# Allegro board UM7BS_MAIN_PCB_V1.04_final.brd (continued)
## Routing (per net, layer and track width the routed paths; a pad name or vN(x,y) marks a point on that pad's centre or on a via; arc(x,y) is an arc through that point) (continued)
USB_OC0#: length 293.4
  TOP w0.102: U1.P16 178.07,56.87 v1(178.07,56.83)
  LAY3 w0.102: v1(178.07,56.83) 178.28,56.63 178.28,56.02 178.07,55.81 177.74,55.81 177.43,55.5 177.43,55.25 174.52,52.34 174.52,50.11 174.68,49.95 174.68,48.47 174.26,48.05 174.26,42.66 175.74,41.18 175.74,40.16 176.23,39.67 v1(176.23,39.43) ; v1(47.45,27.59) 47.45,33.61 43.15,37.92 43.15,37.93 40.23,40.85 40.23,70.1 42.7,72.57 42.7,78.93 37.3,84.34 22.57,84.34 v1(20.42,82.19)
  LAY4 w0.102: v1(174.34,11.42) 172.67,9.75 153.55,9.75 151.07,12.24 146.8,12.24 144.78,10.22 140.71,10.22 140.25,10.68 130.46,10.68 127.77,13.36 115.94,13.36 112.28,9.7 98.55,9.7 95.91,12.35 92.03,12.35 89.42,9.74 70.45,9.74 66.8,13.39 57.24,13.39 54.79,15.85 49.31,15.85 47.45,17.7 v1(47.45,27.59)
  BOTTOM w0.102: v1(174.34,11.42) 174.15,11.62 174.15,15.09 174.79,15.74 174.79,26.85 172.71,28.93 172.71,37.03 174.97,39.28 176.08,39.28 v1(176.23,39.43) ; R89.1 176.42,53.05 176.42,53.41 176.93,53.91 176.93,54.42 177.36,54.85 177.36,55.62 177.54,55.79 178.07,55.79 178.22,55.95 178.22,56.68 v1(178.07,56.83)
  BOTTOM w0.203: U35.3 16.8,85.6 17.42,84.98 R472.1 19.47,84.98 R474.2 20.48,84.98 C441.1 20.49,82.26 v1(20.42,82.19)
USB_OC1#: length 165.5
  TOP w0.102: U1.P14 177.92,56.3 v1(177.82,56.2) ; v1(156.22,78.58) 156.22,76.66 158.04,74.84 158.04,64.4 v1(160.15,62.3)
  LAY3 w0.102: v1(156.22,78.58) 154.35,78.58 153.6,79.34 153.6,81.5 152.95,82.15 151.4,82.15 150.86,81.61 123.33,81.61 122.24,82.7 119.88,82.7 119.04,83.54 67.51,83.54 66.12,84.93 v1(60.08,84.93)
  BOTTOM w0.102: v1(160.15,62.3) 161.56,60.89 161.56,57.27 161.96,56.86 164.29,56.86 165.78,55.37 165.78,53.79 167.07,52.5 167.66,52.5 168.88,51.28 169.75,51.28 R88.1 170.85,52.38 170.85,53.12 171.27,53.54 171.68,53.54 172.5,54.36 172.5,54.69 172.99,55.18 176.24,55.18 177.26,56.2 v1(177.82,56.2) ; R481.2 53.64,91.95 60.08,85.51 v1(60.08,84.93)
  BOTTOM w0.203: R479.1 46.18,91.94 C448.1 ; C448.1 48.72,91.94 R481.2 ; C448.1 47.69,90.53 U38.3
USB_OC2#: length 86.4
  TOP w0.203: v1(42.07,25.66) R484.1 42.07,24.74 43.28,23.53 R486.2 43.48,23.28 C453.1 43.05,22.05 U39.3 ; U40.3 59.27,15.94 C458.1 58.13,17.28 R490.1 R491.2 58.29,20.09 57.4,20.98 57.4,28.21 56.32,29.29 56.32,30.07 57.53,31.29 59.01,31.29 v1(59.51,31.78)
  LAY3 w0.102: v1(61.8,52) 61.8,34.08 v1(59.51,31.78)
  BOTTOM w0.102: R467.1 44.2,55.29 47.63,51.86 61.66,51.86 v1(61.8,52)
  BOTTOM w0.203: v1(42.07,25.66) 42.07,26.48 47.12,31.53 59.26,31.53 v1(59.51,31.78)
USB_PN0: length 177.3
  TOP w0.089: 171.11,69.87 172.21,69.87
  TOP w0.101: 172.21,69.87 U1.B42 ; v1(167.25,74.99) 167.25,75.17 167.46,75.37 167.6,75.37 167.93,75.04 167.93,73.05 171.11,69.87
  TOP w0.124: FIL5.1 9,88.28 9,87.68 v1(9.36,87.32)
  LAY3 w0.112: v1(9.36,87.32) 9.22,87.32 8.83,87.71 8.83,88.1 8.97,88.24 13.42,88.24 13.87,87.79 26.44,87.79 27.97,86.25 49.35,86.25 50.03,86.93 66.65,86.93 68.21,85.37 107.9,85.37 108.38,84.89 117.73,84.89 118.07,85.23 123.26,85.23 124.65,83.84 126.75,83.84 127.06,84.15 139.61,84.15 140.52,83.23 148.17,83.23 148.34,83.39 153.95,83.39 160.55,76.79 164.69,76.79 166.19,75.29 166.72,75.29 166.83,75.18 166.83,74.82 166.93,74.72 167.11,74.72 167.25,74.86 v1(167.25,74.99)
USB_PN1: length 155.6
  TOP w0.101: 168.49,74.39 168.49,74.38 168.5,74.37 168.5,74.29 168.51,74.28 168.51,73.22 170.68,71.05 171.35,71.05 171.56,70.84 171.84,70.84 172.13,70.55 172.25,70.55 172.36,70.65 172.36,70.75 U1.B44
  TOP w0.124: 168.49,74.39 168.49,77.17 v1(168.24,77.42) ; v1(36.28,88.35) 36.28,88.95 FIL15.1
  LAY3 w0.112: v1(36.28,88.35) 36.51,88.58 36.51,88.75 36.42,88.85 35.85,88.85 35.75,88.94 35.75,89.37 35.9,89.52 36.42,89.52 37.07,88.86 49.09,88.86 50.05,89.82 58.89,89.82 59.62,89.1 67.53,89.1 69.36,87.27 90.52,87.27 91.69,88.44 94.28,88.44 95.45,87.27 113.67,87.27 115.5,89.1 124.09,89.1 126.09,87.11 127.89,87.11 129.02,88.24 129.9,88.24 131.02,89.35 135.82,89.35 136.94,88.24 144.64,88.24 147.35,85.52 154.03,85.52 161.19,78.36 167.99,78.36 168.58,77.77 168.58,77.52 168.47,77.42 v1(168.24,77.42)
USB_PN2: length 29.6
  TOP w0.089: 170.73,69.46 171.8,69.46 U1.A41
  TOP w0.102: 170.73,69.46 170.67,69.53 166.66,73.54 166.64,73.54 166.5,73.68 166.5,73.75 166.49,73.76 166.49,73.78
  TOP w0.124: FIL11.2 167.53,88.08 163.03,88.08 161.21,86.26 161.21,82.41 163.57,80.05 163.57,77.92 166.49,75 166.49,73.78
USB_PN3: length 158.5
  TOP w0.101: U1.A45 171.85,71.54 171.74,71.66 171.2,71.66 170.63,72.23 v1(170.39,72.23)
  TOP w0.124: v1(57.87,30.35) 58.12,30.1 58.12,29.72 58.14,29.72 58.14,21.95 59.51,20.58 61.16,20.58 FIL10.1
  LAY3 w0.112: v1(170.39,72.23) 170.15,72.23 169.99,72.39 169.29,72.39 168.74,72.94 159.66,72.94 155.83,69.11 155.83,61.77 151.02,56.97 148.67,56.97 147.12,55.41 112.93,55.41 110.2,58.15 106.19,58.15 100.83,52.78 97.67,52.78 95.25,50.35 84.15,50.35 80.13,46.34 80.13,36.65 73.57,30.09 60.42,30.09 59.67,29.34 58.47,29.34 58.13,29.68 58.13,30.09 v1(57.87,30.35)
USB_PN4: length 173.2
  TOP w0.089: U1.C40 172.67,68.92 172.37,68.62 172.12,68.62 172.01,68.73 171.6,68.73
  TOP w0.101: 166.46,72.61 166.65,72.61 166.72,72.61 170.59,68.73 171.6,68.73
  TOP w0.124: 166.46,72.61 165.67,72.61 164.62,73.66 164.62,74.52 164.91,74.81 v1(165.61,74.81) ; R485.1 45.68,20.42 45.21,20.42 44.7,20.92 44.7,22.8 49.66,27.76 v1(49.66,29.8)
  LAY3 w0.112: v1(49.66,29.8) 49.66,30.74 50.09,31.17 73.08,31.17 78.6,36.69 78.6,46.52 84.16,52.08 92.56,52.08 96.88,56.39 102.39,56.39 105.48,59.49 110.49,59.49 113.55,56.43 146.36,56.43 148.3,58.36 150.92,58.36 154.75,62.2 154.75,69.69 159.3,74.25 163.78,74.25 164.34,74.81 v1(165.61,74.81)
USB_PP0: length 177.3
  TOP w0.089: U1.C42 172.79,70.04 172.51,70.04 172.36,70.19 172.12,70.19 172.03,70.1 171.21,70.1
  TOP w0.101: 171.21,70.1 168.16,73.14 168.16,75.14 167.7,75.6 167.38,75.6 v1(167.25,75.73)
  TOP w0.124: FIL5.4 8.75,88.49 8.75,87.48 v1(8.59,87.32)
  LAY3 w0.112: v1(8.59,87.32) 8.59,88.2 8.87,88.48 13.52,88.48 13.97,88.02 26.54,88.02 28.07,86.49 49.25,86.49 49.93,87.17 66.74,87.17 68.31,85.61 108,85.61 108.48,85.13 117.63,85.13 117.97,85.47 123.36,85.47 124.75,84.08 126.65,84.08 126.96,84.38 139.7,84.38 140.62,83.47 148.08,83.47 148.24,83.63 154.05,83.63 160.65,77.03 164.79,77.03 166.29,75.53 167.06,75.53 v1(167.25,75.73)
USB_PP1: length 155.6
  TOP w0.101: 168.74,74.39 168.74,73.32 170.78,71.27 171.45,71.27 171.66,71.06 172,71.06 172.13,71.19 172.34,71.19 172.6,70.93 U1.C43
  TOP w0.124: v1(35.51,88.35) 35.51,88.88 FIL15.4 ; v1(168.98,77.42) 168.74,77.17 168.74,74.39
  LAY3 w0.112: v1(168.98,77.42) 168.82,77.58 168.82,77.87 168.09,78.6 161.29,78.6 154.13,85.76 147.45,85.76 144.74,88.48 137.04,88.48 135.92,89.59 130.92,89.59 129.8,88.48 128.92,88.48 127.8,87.35 126.18,87.35 124.19,89.34 115.4,89.34 113.57,87.51 95.55,87.51 94.37,88.68 91.59,88.68 90.42,87.51 69.46,87.51 67.63,89.34 59.72,89.34 58.99,90.06 49.95,90.06 48.99,89.1 37.17,89.1 36.52,89.76 35.81,89.76 35.51,89.47 v1(35.51,88.35)
USB_PP2: length 29.5
  TOP w0.089: 170.83,69.69 172.01,69.69 172.21,69.49 172.52,69.49 U1.C41
  TOP w0.102: 170.83,69.69 166.74,73.78
  TOP w0.124: 166.74,73.78 166.74,75.1 163.82,78.03 163.82,80.16 161.46,82.51 161.46,86.16 163.13,87.83 167.61,87.83 FIL11.3
USB_PP3: length 158.5
  TOP w0.101: U1.C45 172.51,71.44 172.28,71.44 171.84,71.88 171.3,71.88 v1(170.39,72.79)
  TOP w0.124: FIL10.4 61.43,20.83 59.62,20.83 58.39,22.05 58.39,29.97 58.39,29.97 58.38,29.97 58.38,30.1 v1(58.63,30.35)
  LAY3 w0.112: v1(58.63,30.35) 58.37,30.09 58.37,29.78 58.57,29.58 59.57,29.58 60.32,30.33 73.47,30.33 79.89,36.75 79.89,46.44 84.05,50.59 95.15,50.59 97.57,53.02 100.73,53.02 106.09,58.38 110.3,58.38 113.03,55.65 147.02,55.65 148.58,57.2 150.92,57.2 155.59,61.87 155.59,69.21 159.56,73.18 168.84,73.18 169.39,72.63 169.99,72.63 170.15,72.79 v1(170.39,72.79)
USB_PP4: length 173.2
  TOP w0.089: 171.6,68.94 171.82,68.94 172.14,69.26 172.34,69.26 172.46,69.13 172.46,69.02 172.37,68.92 U1.B40
  TOP w0.101: 171.6,68.94 170.71,68.94 166.81,72.83 166.49,72.83 166.46,72.86
  TOP w0.124: v1(50.43,29.8) 49.91,29.28 49.91,27.66 44.95,22.69 44.95,21.03 45.31,20.67 45.71,20.67 R483.1 ; 166.46,72.86 165.77,72.86 164.87,73.76 164.87,74.42 165.01,74.56 165.23,74.56 v1(165.61,74.18)
  LAY3 w0.112: v1(165.61,74.18) 165.61,74.1 165.44,73.94 165.24,73.94 165.13,74.05 165.13,74.47 165.02,74.57 164.44,74.57 163.88,74.01 159.4,74.01 154.99,69.59 154.99,62.1 151.02,58.13 148.4,58.13 146.46,56.19 113.45,56.19 110.39,59.25 105.58,59.25 102.49,56.15 96.98,56.15 92.66,51.84 84.25,51.84 78.84,46.43 78.84,36.59 73.18,30.93 50.19,30.93 49.9,30.64 49.9,30.32 49.98,30.24 50.48,30.24 50.6,30.12 50.6,29.93 50.47,29.8 v1(50.43,29.8)
V_DAC: length 12.6
  TOP w0.406: v1(107.81,38.41) C358.2 107.8,37.79 U23.6 ; v1(107.79,34.6) C350.2 107.78,33.98 U23.3
  BOTTOM w0.406: U24.6 107.78,35.24 C351.2 ; U24.3 107.81,39.05 C359.2 107.81,38.41 v1(107.81,38.41)
  BOTTOM w0.508: v1(107.81,38.41) 107.78,38.38 C351.2 107.79,35.24 v1(107.79,34.6)
VCLK: length 26.9
  BOTTOM w0.114: C177.1 C178.1 115.17,55.57 125.63,55.57 127.86,57.8 127.86,59.85 127.35,60.35 124.12,60.35 123.12,61.36 U10.19
VFB1: length 3.5
  BOTTOM w0.178: 122.04,59.62 121.9,59.62 121.6,59.93 U10.2
  BOTTOM w0.508: 122.04,59.62 122.23,59.62 122.75,59.1 R179.1 123.62,58.66 R180.2
VFB2: length 3.3
  BOTTOM w0.178: 120.63,59.41 120.63,59.51 120.8,59.68 U10.4
  BOTTOM w0.406: R181.1 120.44,59.22 120.63,59.41
  BOTTOM w0.508: R181.1 120.33,58.45 R183.1
VGG_GND: length 11.7
  TOP w0.178: v1(156.08,23.3) 156.24,23.3 156.35,23.19 U11.6
  TOP w0.406: R839.2 150.89,28.32 151.91,29.34 v1(153.03,29.34)
  LAY3 w0.406: v1(153.03,29.34) 153.65,28.72 153.65,25.91 156.08,23.48 v1(156.08,23.3)
VGG_LX: length 11
  TOP w0.178: U11.4 156.54,23.99 156.39,24.14 155.51,24.14 155.42,24.23
  TOP w0.305: 155.05,24.6 155.42,24.23
  TOP w0.635: 155.05,24.6 155.05,25.11 154.43,25.73 C211.2 154.18,27.55 154.76,28.13 154.76,31.99 155.13,32.36
VGG_SENSEN: length 94.7
  TOP w0.254: v1(156.39,26.71) 156.36,26.74 R826.1
  LAY3 w0.203: v1(191.36,37.52) 191.56,37.52 194.38,40.34 194.38,43.96 v1(193.94,44.4)
  LAY4 w0.203: v1(156.39,26.71) 156.83,26.27 156.83,25.5 157.29,25.03 157.29,22.01 156.48,21.2 153.89,21.2 v1(152.54,19.85)
  BOTTOM w0.203: v1(152.54,19.85) 152.05,20.33 151.63,20.33 151.31,20 151.31,17.95 151.6,17.65 151.6,15.47 151.21,15.09 151.21,11.99 152.97,10.23 183.05,10.23 187.79,14.97 187.79,23.36 191.36,26.92 v1(191.36,37.52) ; R770.2 194.08,44.54 v1(193.94,44.4)
VGG_SENSEN_R: length 22.2
  TOP w0.254: v1(182.88,59.95) 183.26,60.33 U1.AD22
  LAY3 w0.102: 187.21,59.64 187.21,60.11 186.99,60.33 183.26,60.33 v1(182.88,59.95)
  LAY3 w0.203: v1(193,47.05) 191.84,48.2 191.84,51.62 189.07,54.39 189.07,57.48 188.29,58.26 188.29,58.56 187.21,59.64
  BOTTOM w0.203: R770.1 194.08,46.74 193.78,47.05 v1(193,47.05)
VGG_SENSEP: length 91.3
  TOP w0.254: v1(156.04,26.12) 155.56,26.59 R105.1
  LAY3 w0.203: v1(194.57,44.87) 194.68,44.76 194.68,40.21 v1(190.87,36.4)
  LAY4 w0.203: v1(151.89,19.86) 153.53,21.5 156.36,21.5 156.99,22.13 156.99,24.9 156.48,25.42 156.48,25.68 v1(156.04,26.12)
  BOTTOM w0.203: R848.2 194.85,45.16 v1(194.57,44.87) ; v1(190.87,36.4) 190.87,27.15 187.38,23.66 187.38,15.24 182.67,10.53 153.09,10.53 151.52,12.11 151.52,14.68 151.96,15.13 151.96,18.15 151.62,18.49 151.62,19.59 v1(151.89,19.86)
VGG_SENSEP_R: length 23.5
  TOP w0.254: U1.AD24 183.26,61.09 v1(182.88,60.71)
  LAY3 w0.203: v1(182.88,60.71) 183.45,61.28 186.39,61.28 187.11,60.56 187.68,60.56 188.78,59.46 188.78,58.31 190.01,57.08 190.01,53.99 192.18,51.82 192.18,48.49 v1(193.02,47.65)
  BOTTOM w0.203: R848.1 194.85,46.7 194.11,47.44 193.23,47.44 v1(193.02,47.65)
VNN_SVID_SENSEP: length 42.2
  LAY3 w0.203: v1(171.07,39.7) 171.07,38.95 175.54,34.48 189.71,34.48 195.01,39.78 195.01,46.66 193.4,48.27 v1(193.05,48.27)
  BOTTOM w0.203: R109.1 168.07,40.07 170.7,40.07 v1(171.07,39.7) ; R565.2 193.23,48.09 v1(193.05,48.27)
VREFA: length 3.8
  BOTTOM w0.305: U41.12 117.26,85.55 C992.1 117.26,85.79 116.77,86.28 116.28,86.28 115.92,86.64 R616.2
VREG3: length 76.7
  TOP w0.406: v1(126.49,58.8) 125.5,57.82 v1(121.71,57.82) 121.45,57.82 v1(119.6,59.67)
  LAY3 w0.508: v1(118.7,80.09) 118.11,80.68 115.53,80.68 114.92,80.07 104.57,80.07 103.93,79.43 102.58,79.43 100.16,77.01 88.73,77.01 86.8,78.94 v1(84.51,78.94)
  LAY4 w0.508: v1(121.71,57.82) 119.94,57.82 117.64,60.11 117.64,73.52 118.7,74.57 v1(118.7,80.09)
  BOTTOM w0.178: 121.25,59.44 121.2,59.49 U10.3
  BOTTOM w0.381: v1(119.6,59.67) 118.18,59.67 R186.1
  BOTTOM w0.406: v1(126.49,58.8) 127.05,59.36 R185.2
  BOTTOM w0.508: v1(121.71,57.82) C156.1 121.71,58.98 121.25,59.44 ; D29.P v1(84.51,78.94)
VREG5: length 1.8
  BOTTOM w0.203: U10.13 121.2,63.87 121.64,64.31 C175.2
VSPI_KBC: length 15.1
  TOP w0.305: R460.2 U34.8 C427.1 R457.1 D12.N 44.36,77.6 v1(44.79,77.16) 45.48,76.47 R461.2
  BOTTOM w0.305: R449.1 49.05,75.87 47.76,77.16 v1(44.79,77.16)
WAKE_SCI_EC: length 16.8
  TOP w0.102: v1(65.56,65.08) 66.38,65.08 68.07,63.38 73.33,63.38 v1(74.54,62.16)
  TOP w0.114: R433.2 75.89,63.52 v1(74.54,62.16)
  BOTTOM w0.114: R438.1 v1(65.56,65.08) ; v1(74.54,62.16) 74.54,62.32 R434.1 75.78,63.56 U32.9
WIFI_3P3_RST#: length 2.8
  BOTTOM w0.102: U27.1 226.66,19.31 R364.2 226.04,21.27 Q39.3
WIFI_PCIE_RST: length 95.2
  TOP w0.114: U1.V12 180.57,54.68 v1(180.74,54.68)
  LAY3 w0.102: v1(201.13,23.77) 190.88,34.03 175,34.03 170.44,38.58 170.44,40.12 167.49,43.08 165.48,43.08 v1(164.25,44.31)
  LAY4 w0.102: v1(201.13,23.77) 218.76,23.77 221.71,20.82 v1(222.91,20.82)
  BOTTOM w0.101: 175.16,46.09 174.57,46.09
  BOTTOM w0.102: 174.57,46.09 171.61,43.14 165.44,43.14 164.26,44.31 v1(164.25,44.31) ; Q40.1 222.97,20.77 v1(222.91,20.82)
  BOTTOM w0.114: v1(180.74,54.68) 179.84,53.78 179.84,49.57 179.1,48.82 178.38,48.82 R115.1 178.3,48.57 178.06,48.33 177.39,48.33 175.16,46.09
WIFI_PERST#: length 3.5
  TOP w0.102: CN26.52 v1(229.57,16.02)
  BOTTOM w0.102: R372.1 228.57,16.02 v1(229.57,16.02)
  BOTTOM w0.114: U27.4 228.56,16.63 228.51,16.59 R372.1
WIFI_PWRON: length 244.6
  LAY3 w0.102: v1(52.52,68.74) 52.52,52.83 53.47,51.89 53.47,37.31 v1(53.13,36.97)
  LAY4 w0.102: v1(215.79,11.71) 214.45,10.38 183.21,10.38 180.73,12.86 173.11,12.86 170.91,10.67 154.81,10.67 152.84,12.64 152.31,12.64 151.22,13.72 145.87,13.72 143.38,11.23 141.22,11.23 140.67,11.78 130.5,11.78 127.38,14.91 110.4,14.91 106.37,18.94 106.37,45.76 104.43,47.7 98.07,47.7 88.11,37.74 70.7,37.74 68.55,35.59 58.97,35.59 57.59,36.97 v1(53.13,36.97)
  BOTTOM w0.102: v1(215.79,11.71) 218.06,11.71 218.2,11.85 R380.2 218.2,12.67 218.89,13.36 U28.3
  BOTTOM w0.114: U31.112 53.93,70.14 v1(52.52,68.74)
WIFI_RF_KILL_R*: length 2.1
  TOP w0.102: CN26.56 229.54,15.02 v1(229.37,15.19)
  BOTTOM w0.102: v1(229.37,15.19) 228.6,15.19 R193.1
WIRELESS_ON: length 235.5
  LAY3 w0.102: v1(60.33,54.14) 60.33,34.15 v1(60.02,33.84)
  LAY4 w0.102: v1(224.33,16.89) 224.33,14.67 219.83,10.16 182.89,10.16 180.51,12.55 173.26,12.55 171.18,10.46 154.68,10.46 152.75,12.39 152.06,12.39 150.94,13.51 145.99,13.51 143.49,11.02 141.11,11.02 140.71,11.42 130.58,11.42 127.31,14.69 110.25,14.69 105.94,19 105.94,45.7 104.31,47.34 98.04,47.34 87.99,37.29 72.34,37.29 68.89,33.84 v1(60.02,33.84)
  BOTTOM w0.102: R193.2 226,15.18 224.33,16.85 v1(224.33,16.89)
  BOTTOM w0.114: v1(60.33,54.14) U31.33
WP#: length 30.2
  TOP w0.102: v1(158.93,39.99) 159.11,40.18 U2.3 U4.3
  TOP w0.114: v1(179.6,48.2) 179.6,48.27 179.78,48.45 U1.U1
  BOTTOM w0.102: 160.6,41.6 158.48,41.6 158.26,41.39 R40.1
  BOTTOM w0.114: R40.1 158.93,40.4 v1(158.93,39.99) ; 160.6,41.6 162.6,43.6 164.12,43.6 165.06,42.65 171.95,42.65 174.11,44.82 175.13,44.82 176.68,46.36 176.68,46.84 177.69,47.86 179.26,47.86 v1(179.6,48.2)
WRST#: length 9.2
  TOP w0.102: v1(60.71,64.09) C422.2 R445.1 SW2.3 60.96,61.82 60.77,62 58.77,62 58.58,61.82 SW2.1
  BOTTOM w0.114: U31.14 60.98,65.06 60.71,64.79 v1(60.71,64.09)
XTAL1: length 8.2
  BOTTOM w0.114: X5.1 121.56,29.96 121.56,31.08 121.03,31.62 120.55,31.62 120.17,32 120.17,33.36 C324.1 120.73,33.92 U22.43
XTAL2: length 6
  BOTTOM w0.114: X5.3 120.34,30.94 119.15,32.13 119.15,33.36 C323.1 120.33,34.54 U22.44
XTAL25M_IN: length 18.5
  TOP w0.102: v1(177.44,60.64) 177.78,60.64 178.29,61.16 U1.P24
  TOP w0.114: X1.1 165.73,65.98 165.73,64.49 C12.2 166.27,63.07 R45.2 166.15,62.94 v1(166.15,62.46)
  LAY3 w0.127: v1(166.15,62.46) 167.09,61.51 171.81,61.51 172.05,61.27 176.81,61.27 v1(177.44,60.64)
XTAL25M_OUT: length 16.4
  TOP w0.114: X1.3 165.31,65.24 165.43,65.13 165.43,64.13 C13.2 165.26,63.14 R45.1 165.51,62.88 v1(165.51,62.46)
  TOP w0.127: U1.M22 177.05,60.27 v1(176.67,60.64)
  LAY3 w0.127: v1(176.67,60.64) 176.28,61.03 171.68,61.03 171.53,61.19 166.78,61.19 v1(165.51,62.46)
N46460: length 1.3
  TOP w0.114: v1(191.41,63.57) 191.41,63.38 U1.BA28
  BOTTOM w0.114: v1(191.41,63.57) 191.44,63.53 R1.1
N52618: length 1.3
  TOP w0.102: U1.G38 174.64,68.22 v1(174.64,68.39)
  BOTTOM w0.102: v1(174.64,68.39) 174.64,67.98 R15.2
N52622: length 1.3
  TOP w0.102: v1(174.01,68.42) 174.01,68.14 U1.F38
  BOTTOM w0.102: R15.1 174.01,67.85 v1(174.01,68.42)
N53865: length 1.2
  TOP w0.102: v1(174.77,73.6) 174.37,73.2 U1.F49
  BOTTOM w0.102: v1(174.77,73.6) 174.74,73.57 R17.2
N53869: length 1.2
  TOP w0.102: v1(174.77,72.71) 174.38,72.32 U1.F47
  BOTTOM w0.102: v1(174.77,72.71) 174.23,72.71 R17.1
N59327: length 2.4
  TOP w0.114: v1(178.79,71.25) 178.65,71.25 U1.P44
  BOTTOM w0.114: v1(178.79,71.25) 178.96,71.43 178.96,72.42 R16.1
N59478: length 6.6
  TOP w0.102: v1(177.82,55.31) 178.21,55.7 U1.P13
  BOTTOM w0.102: R20.1 178.4,50.33 178.4,54.73 v1(177.82,55.31)
N59568: length 5.1
  TOP w0.102: U1.P12 178.13,54.99 v1(177.82,54.68)
  BOTTOM w0.102: R21.1 177.33,51.15 177.33,54.19 v1(177.82,54.68)
N60711: length 3.8
  TOP w0.101: C4.1 169.46,61.06 169.56,61.16 169.56,61.52 169.67,61.62 169.92,61.62 170.42,61.12 172.03,61.12 172.04,61.13 172.22,61.13 U1.B24
N60715: length 4.2
  TOP w0.101: U1.C24 172.65,61.15 172.36,61.44 172.12,61.44 172.03,61.35 170.52,61.35 170.02,61.85 C3.1
N61460: length 12.4
  TOP w0.101: U1.C25 172.31,61.64 171.83,62.12 171,62.12 168.73,64.38 168.73,64.6 168.75,64.61 168.75,64.63
  TOP w0.124: C6.1 165.65,69.21 165.88,68.98 167.42,68.98 168.75,67.65 168.75,64.63
N61464: length 11.7
  TOP w0.101: U1.A25 171.85,61.77 171.73,61.89 170.9,61.89 168.49,64.3 168.49,64.63
  TOP w0.124: C5.1 165.65,68.44 165.94,68.73 167.31,68.73 168.49,67.55 168.49,64.63
N61983: length 12.2
  TOP w0.089: U1.AM14 186.74,56.07 v1(186.58,56.07)
  BOTTOM w0.114: v1(186.58,56.07) 186.07,55.56 186.07,52.33 185.79,52.05 185.79,51.67 187.09,50.38 187.09,49.13 189.63,46.59 R28.1
N61987: length 15.7
  TOP w0.089: v1(185.56,55.95) 186.03,56.41 U1.AK14
  BOTTOM w0.114: v1(185.56,55.95) 186.12,56.5 186.74,56.5 188.31,54.93 188.87,54.93 189.45,54.35 189.45,53.61 191.18,51.88 191.41,51.88 192.17,51.12 192.17,49.21 192.55,48.84 192.55,46.73 192.88,46.39 R29.1
N62557: length 1.3
  TOP w0.102: v1(173.88,61.66) 174.26,62.04 U1.F26
  BOTTOM w0.102: v1(173.88,61.66) 173.88,62.2 R35.2
N62561: length 1.4
  TOP w0.102: U1.D26 173.6,62.14 v1(173.12,61.66)
  BOTTOM w0.102: R35.1 173.02,61.75 v1(173.12,61.66)
N64250: length 1.9
  TOP w0.102: v1(176.67,64.58) 177.05,64.21 U1.M30
  BOTTOM w0.114: v1(176.67,64.58) 175.91,65.34 R25.2
N64254: length 1.7
  TOP w0.102: v1(177.31,64.58) 177.76,64.13 U1.N30
  BOTTOM w0.114: R25.1 176.77,65.12 v1(177.31,64.58)
N64675: length 4
  TOP w0.114: U1.AG1 184.92,49.52 184.92,49.09 R24.1
N64950: length 9.9
  TOP w0.114: U1.AF13 184.16,55.7 v1(184.55,55.31)
  BOTTOM w0.114: v1(184.55,55.31) 183.83,54.59 183.83,50.25 184.47,49.62 184.47,48 C7.1 R30.1
N65002: length 7.2
  TOP w0.114: U1.AF12 184.55,54.58 v1(184.55,54.55)
  BOTTOM w0.114: R33.1 184.94,48.94 184.74,49.14 184.74,50.33 184.12,50.95 184.12,54.12 v1(184.55,54.55)
N65040: length 5.9
  TOP w0.114: v1(182.77,53.28) 183.06,53.57 U1.AD9
  BOTTOM w0.114: R31.1 182.02,49.22 183.19,50.39 183.19,52.86 v1(182.77,53.28)
N65098: length 2.2
  TOP w0.114: U1.AD7 182.85,52.52 v1(182.77,52.52)
  BOTTOM w0.114: v1(182.77,52.52) 182.2,51.94 R32.1
N65529: length 8.8
  TOP w0.114: v1(184.55,56.07) 184.48,56.07 U1.AF14
  BOTTOM w0.114: R34.1 182.83,49.24 183.57,49.98 183.57,55.09 v1(184.55,56.07)
N66939: length 1.3
  TOP w0.203: U3.6 152.13,43.23 C10.2
N72611: length 1.2
  TOP w0.114: U1.P20 178.81,59.53 v1(178.81,59.63)
  BOTTOM w0.102: R46.2 178.81,59.81 v1(178.81,59.63)
N72676: length 8
  TOP w0.102: v1(178.07,59.63) 177.76,59.32 U1.N20
  BOTTOM w0.102: v1(178.07,59.63) 177.93,59.77 177.93,60.74 177.54,61.13 172.46,61.13 172.16,61.44 R47.2
N73559: length 44.4
  TOP w0.102: v1(177.45,61.66) 177.79,61.66 178.26,62.13 U1.P26
  LAY3 w0.127: v1(177.45,61.66) 177.45,61.74 177.09,62.1 168.94,62.1 v1(167.94,63.1)
  LAY4 w0.102: v1(167.94,63.1) 167.35,63.69 167.35,66.7 168.08,67.43 168.08,71.88 170,73.79 170,78.79 172.63,81.42 177.09,81.42 179.31,79.2 181.79,79.2 v1(182.87,80.28)
  BOTTOM w0.102: v1(182.87,80.28) 182.87,80.28 R44.2
N73565: length 7
  TOP w0.102: U1.AH45 185.23,71.65 v1(185.56,71.31)
  BOTTOM w0.114: R48.2 183.98,76.53 183.98,72.77 184.55,72.2 184.8,72.2 185.56,71.44 v1(185.56,71.31)
N73585: length 1.7
  BOTTOM w0.089: R49.2 183.68,78.64
  BOTTOM w0.102: R44.1 R49.2
  BOTTOM w0.114: 183.68,78.64 R48.1
N73829: length 4.7
  TOP w0.089: U1.A9 170.8,53.77 170.74,53.72 168.59,53.72 168.41,53.89
  TOP w0.102: 168.41,53.89 168.39,53.92 168.39,54.59 R50.2
N73942: length 9.1
  TOP w0.102: U1.AD51 183.19,74.63 183.53,74.97 183.53,75.1 183.39,75.24 183.39,75.74 183.02,76.11 183.02,76.65 182.64,77.03
  TOP w0.114: R51.2 179.46,81.19 R52.2 179.46,80.21 182.64,77.03
N74220: length 9
  TOP w0.102: 182.75,76.37 182.75,76.1 183.18,75.66 U1.AD52
  TOP w0.114: 182.75,76.37 182.75,76.49 180.87,78.36 180.08,78.36 178.93,79.52 178.93,80.3 178.52,80.71 R56.1 R53.2
N74266: length 13.4
  TOP w0.102: U1.AH50 185.39,73.47 v1(185.56,73.47)
  BOTTOM w0.102: R57.1 186.34,82.96 186.34,83.94 185.95,84.33 R54.2
  BOTTOM w0.114: v1(185.56,73.47) 184.5,74.54 184.5,81.12 R57.1
N74833: length 13.7
  TOP w0.102: U1.AH48 185.2,73.07 v1(185.56,72.71)
  BOTTOM w0.114: v1(185.56,72.71) 184.23,74.05 184.23,82.04 184.49,82.3 184.49,83.85 184.93,84.29 R55.1
N75113: length 11.4
  TOP w0.102: U1.AH51 185.32,74.53 185.32,74.8 185.44,74.92 185.44,75.16 185.33,75.26 185.33,78.02 ; R59.1 185.51,82.44 185.51,84.5 R58.2
  TOP w0.114: 185.33,78.02 185.33,81.07 185.95,81.68 R59.1
N75766: length 14.1
  TOP w0.114: R63.1 v1(184.93,83.63)
  LAY4 w0.102: v1(184.93,83.63) 184.93,84.45 183.66,85.72 183.26,85.72 176.92,92.05 v1(176.92,92.48)
  BOTTOM w0.102: Q5.3 v1(176.92,92.48)
N77258: length 5.2
  TOP w0.102: U1.AH40 185.21,68.8 v1(185.56,69.15)
  BOTTOM w0.102: v1(185.56,69.15) 185.13,69.59 185.13,71.53 184.72,71.95 184.2,71.95 R60.2
N79829: length 1.7
  BOTTOM w0.114: U5.5 114.6,44.81 114.97,44.44 115.14,44.44 115.27,44.31 R72.1
N80354: length 12.8
  TOP w0.102: v1(186.58,53.28) 186.79,53.28 U1.AM9
  BOTTOM w0.114: v1(186.58,53.28) 188.28,51.58 188.66,51.58 188.99,51.25 188.99,50.36 190.01,49.34 190.01,48.83 191.34,47.5 191.34,43.91 R65.1
N81322: length 1.9
  TOP w0.102: v1(173.88,65.6) 174.2,65.92 U1.F34
  BOTTOM w0.102: v1(173.88,65.6) 174.01,65.6 174.77,66.36 R94.2
N81326: length 1.6
  TOP w0.102: U1.D34 173.53,65.93 v1(173.19,65.6)
  BOTTOM w0.102: v1(173.19,65.6) 173.25,65.6 173.91,66.27 R94.1
N82446: length 3.1
  TOP w0.102: U1.B47 172.34,72.56 171.73,72.56 171.1,73.19 v1(171.1,73.19)
  BOTTOM w0.089: v1(171.1,73.19) 169.91,73.19 R91.1
N82527: length 2.6
  TOP w0.102: U1.A48 171.85,73.06 v1(171.1,73.82)
  BOTTOM w0.089: R92.1 v1(171.1,73.82)
N82633: length 1.4
  TOP w0.254: v1(177.44,67.5) 177.44,67.62 U1.N38
  BOTTOM w0.381: R100.2 177.02,67.09 v1(177.44,67.5)
N83371: length 3.7
  TOP w0.102: v1(176.93,55.31) 177.32,55.7 U1.M13
  BOTTOM w0.102: v1(176.93,55.31) 176.55,54.93 176.55,53.91 176.29,53.66 175.47,53.66 R80.2
N83609: length 1.6
  TOP w0.102: v1(178.83,51.88) 179.24,51.47 U1.T4
  BOTTOM w0.114: R93.2 179.09,51.63 v1(178.83,51.88)
N83745: length 3.6
  TOP w0.102: R85.2 177.69,47.38 178.32,48.02 U1.P2
N83769: length 3.3
  TOP w0.102: U1.R3 178.71,50.44 178.71,50.13 178.53,49.95 178.53,47.4 R87.2
N86700: length 19.2
  TOP w0.102: v1(175.91,57.72) 175.91,57.82 U1.K18
  LAY3 w0.127: v1(175.91,57.72) 175.4,58.23 172.99,58.23 172.1,57.34 172.1,56.96 171.34,56.2 166.05,56.2 v1(164.81,54.95)
  BOTTOM w0.114: v1(164.81,54.95) 164.62,55.14 R81.1 163.45,55.14 C20.2 163.44,55.26 162.88,55.82 161.59,55.82 161.11,55.34 X3.2
N86712: length 16.6
  TOP w0.102: U1.M18 176.67,57.87 v1(176.67,57.72)
  LAY3 w0.127: v1(176.67,57.72) 176.2,57.24 172.71,57.24 171.38,55.91 166.46,55.91 v1(164.79,54.24)
  BOTTOM w0.114: v1(164.79,54.24) 164.72,54.17 164.25,54.17 R81.2 163.44,54.19 C16.2 163.28,54.04 X3.1
N87028: length 4.9
  TOP w0.102: U1.F16 173.88,56.95 v1(173.88,56.83)
  BOTTOM w0.102: v1(173.88,56.83) 173.49,56.44 172.86,56.44
  BOTTOM w0.114: 172.86,56.44 172.11,56.44 170.77,55.11 C17.2
N87161: length 5
  TOP w0.102: U1.D18 173.25,57.93 v1(173.25,57.72)
  BOTTOM w0.114: v1(173.25,57.72) 173.14,57.62 171.07,57.62 R79.1 170.08,58.6 C19.1
N88012: length 6.9
  TOP w0.102: U1.J16 175.28,56.92 v1(175.28,56.83)
  BOTTOM w0.102: v1(175.28,56.83) 174.86,57.25 173.64,57.25
  BOTTOM w0.114: 173.64,57.25 170.4,57.25 R83.1 170.07,56.93 C18.1
N88403: length 2.5
  TOP w0.102: U1.G18 174.52,57.85 v1(174.52,57.72)
  BOTTOM w0.102: v1(174.52,57.72) 173.63,58.61 R84.1
N89664: length 20.9
  TOP w0.102: v1(177.44,56.83) 177.44,56.95 U1.N16
  BOTTOM w0.102: v1(177.44,56.83) 177.44,56.67 176.21,55.44 172.92,55.44 172.28,54.8 172.28,54.51 171.55,53.78 171.07,53.78 170.56,53.27 170.56,52.9 R90.1 169.72,53.03 166.83,53.03 166.02,53.84 166.02,55.51 163.66,57.86 Q53.2
N89704: length 3
  TOP w0.102: TP5.1 169.35,55.11
  TOP w0.114: U1.B12 172.14,55.22 171.03,55.22 170.92,55.11 169.35,55.11
N89904: length 2.6
  TOP w0.102: U1.AD40 183.12,68.8 v1(182.77,69.15)
  BOTTOM w0.114: v1(182.77,69.15) 182.77,69.66 182.11,70.33 R111.1
N912733: length 1.2
  TOP w0.089: v1(182.1,64.5) 182.09,64.5 U1.AA30
  BOTTOM w0.381: v1(182.1,64.5) 182,64.4 R129.1
N926610: length 2.9
  TOP w0.254: 174.95,49.22 174.95,49.75 U1.G1
  TOP w0.381: v1(174.92,47.66) C105.1 174.38,48.05 174.95,48.61 174.95,49.22
N936455: length 1.4
  TOP w0.114: v1(171.23,50.66) U1.A3
  BOTTOM w0.102: R135.1 171.29,50.72 v1(171.23,50.66)
N964422: length 1.6
  BOTTOM w0.203: LED1.1 178.04,97.37 U7.4
N967359: length 1.1
  BOTTOM w0.203: LED1.2 176.53,97.37 R145.2
N1003987: length 3
  TOP w0.114: CN1.198 v1(218.61,39.85)
  BOTTOM w0.203: v1(218.61,39.85) 218.74,39.98 R149.2 R146.2
N1049332: length 7.2
  BOTTOM w0.114: Q35.3 117.24,46.31 R308.2 119.72,45.94 119.72,43.08 119.93,42.87 U22.16
N1051586: length 2.5
  BOTTOM w0.102: R296.1 109.96,28.15 U21.4 C334.2
N1052520: length 12.9
  BOTTOM w0.102: CN6.7 86.06,23.78 85.64,24.2 85.64,27.58 88.75,30.7 90.43,30.7 90.83,31.1 90.83,31.5 FIL4.3
N1052530: length 6.1
  BOTTOM w0.102: FIL3.3 92.29,21.1 92.13,20.93 92.13,20.48 92.05,20.4 88.33,20.4 88.23,20.5 88.23,20.78 87.77,21.24 CN6.5
N1052610: length 17.2
  TOP w0.102: FIL2.2 93.42,32.57 93.07,32.22 92.57,32.22 92.28,31.92 92.28,28.36 91.32,27.41 91.32,22.57 89.5,20.75 88.77,20.75 88.52,21 88.52,21.57 CN6.6
N1052618: length 24.9
  TOP w0.102: FIL1.3 90.92,31.04 90.85,31.04 90.74,30.94 90.74,30.68 90.25,30.18 88.81,30.18 86.03,27.4 86.03,15.49 86.42,15.11 88.28,15.11 88.7,15.53 88.7,16.56 88.45,16.81 87.93,16.81 87.59,16.46 CN6.1
N1052644: length 25.7
  TOP w0.102: FIL1.2 90.44,30.8 90.12,30.48 88.69,30.48 85.73,27.52 85.73,15.37 86.29,14.81 88.41,14.81 89,15.4 89,16.68 88.57,17.11 87.91,17.11 CN6.2
N1052708: length 17.2
  TOP w0.102: FIL2.3 93.42,31.57 93.07,31.92 92.7,31.92 92.58,31.8 92.58,28.24 91.62,27.28 91.62,22.44 89.63,20.45 88.74,20.45 88.52,20.22 88.52,19.62 CN6.3
N1052848: length 5.1
  BOTTOM w0.102: CN6.4 87.72,20.1 FIL3.2
N1052868: length 13.3
  BOTTOM w0.102: FIL4.2 91.52,31.72 91.13,31.33 91.13,30.97 90.55,30.4 88.87,30.4 85.94,27.46 85.94,24.33 86.19,24.08 86.81,24.08 86.95,24.22 86.95,24.89 87.11,25.05 CN6.8
N1061129: length 2.1
  BOTTOM w0.178: R331.2 19.98,35.84 U25.33
N1061133: length 2.4
  BOTTOM w0.178: R332.2 19.93,34.89 20.54,35.5 21.3,35.5 21.36,35.44 U25.32
N1061141: length 2.3
  BOTTOM w0.203: C364.1 20.24,36.24 U25.34
N1061235: length 1.5
  BOTTOM w0.178: U25.1 28.86,37.04 C387.2
N1062073: length 6.4
  BOTTOM w0.178: R339.2 R340.2 26.76,28 27.32,28.56 27.32,31.08 27.03,31.38 U25.13
N1062173: length 3.4
  BOTTOM w0.178: U25.20 24.23,31.59 23.44,30.8 22.63,30.8 21.91,30.08 C378.2
N1062273: length 2.5
  BOTTOM w0.178: C379.2 24.63,31.58 U25.19
N1062851: length 6.3
  BOTTOM w0.102: R351.2 38.57,35.14 38.57,33 38.24,32.66 Q37.3 ; R351.2 39.17,35.75 U26.2 ; R351.2 39.17,36.57 R358.2
N1062939: length 1.3
  BOTTOM w0.102: Q38.1 R359.1
N1063057: length 5.9
  BOTTOM w0.102: Q37.1 36.98,31.71 37.27,31.42 R353.2 40.91,31.42 Q38.3
N1063545: length 6.8
  BOTTOM w0.114: U25.12 27.73,31.79 28.05,31.47 28.36,31.47 31.34,28.49 C384.2
N1063553: length 1.7
  BOTTOM w0.102: R342.1 32.19,27.44 R341.2 32.12,26.58 C384.1
N1064125: length 2.4
  BOTTOM w0.114: U25.7 28.84,34.64 29.4,34.08 C385.2
N1064657: length 1.9
  BOTTOM w0.178: R338.1 26.7,31.04 26.23,31.51 U25.15
N1064691: length 4
  BOTTOM w0.178: C375.1 20.75,39.39 20.75,38.73 21.73,37.74 U25.37
N1064695: length 7.9
  BOTTOM w0.178: U25.35 21.39,36.64 20.71,37.33 18.41,37.33 17.31,38.43 17.31,39.59 17.88,40.16 C375.2
N1064865: length 3
  BOTTOM w0.203: U25.27 21.32,33.44 19.72,31.84 C366.1
N1091368: length 1.5
  BOTTOM w0.305: R500.2 132.1,21.44 Q46.3
N1091486: length 2.6
  BOTTOM w0.508: Q45.3 135.47,27.56 R497.1
N1121703: length 9.5
  BOTTOM w0.114: X6.4 X7.2 63.15,74.38 R459.1 62.73,73.97 C425.1 62.22,72.32 60.87,70.97 60.87,70.09 61.1,69.86 U31.2
N1122397: length 9.7
  BOTTOM w0.114: X6.1 X7.1 63.4,75.58 R459.2 62.48,76 R458.2 C423.1 61.71,74.6 60.98,74.6 60.51,74.12 60.51,73.74 60.33,73.56 U31.128
N1123071: length 2.2
  BOTTOM w0.102: U31.93 44.32,69.06 R411.1
N1123827: length 2.6
  BOTTOM w0.114: U31.12 62.82,65.86 C424.1
N1123831: length 4.6
  BOTTOM w0.114: Q42.1 71.08,68.73 R413.2 71.86,67.09 Q43.3
N1124299: length 3.7
  BOTTOM w0.102: R450.1 51.23,74.26 51.23,73.85
  BOTTOM w0.114: 51.23,73.85 52.12,72.96 52.33,72.96 52.73,72.57 U31.109
N1124955: length 2.5
  BOTTOM w0.114: R442.2 58.95,73.3 58.73,73.08 U31.124
N1125039: length 1.6
  BOTTOM w0.114: R386.2 75.9,72.46 U29.5
N1125207: length 2.4
  BOTTOM w0.102: U31.84 45.1,65.46 44.58,65.97 R397.1
N1125735: length 3.9
  BOTTOM w0.114: U31.106 51.53,72.5 50.95,73.08 50.1,73.08 R449.2
N1125963: length 2.2
  BOTTOM w0.114: R428.1 63.8,61.86 U31.22
N1126063: length 9.2
  BOTTOM w0.178: 62.89,66.63 62.52,66.26 U31.11
  BOTTOM w0.203: D8.N 67.33,67.76 67.09,67.51 64.61,67.51 64.04,68.08 R410.1
  BOTTOM w0.381: 62.89,66.63 62.89,67.62 63.52,68.25 R410.1 R409.1
N1126133: length 6.2
  BOTTOM w0.114: R400.1 50.44,75.9 50.44,74.63 R403.1 50.67,73.39 51.17,73.39 51.93,72.63 U31.107
N1126239: length 5.2
  BOTTOM w0.102: D10.N 64.94,60.68 65.85,59.77 R430.2
  BOTTOM w0.114: U31.23 62.8,61.46 63.58,60.68 D10.N
N1126307: length 5.5
  BOTTOM w0.203: R444.1 59.46,75.9 59.46,74.63 R446.1 59.97,73.75 59.13,72.91 U31.125
N1126437: length 7.6
  BOTTOM w0.114: D11.N 67.46,71.81 66.95,71.3 64.16,71.3 63.94,71.08 R431.2 63.4,70.25 63.4,70.09 62.37,69.06 U31.4
N1126855: length 2.6
  BOTTOM w0.114: U31.113 54.33,73.67 R462.1
N1127021: length 5.1
  BOTTOM w0.114: R463.1 58.44,75.9 58.44,72.95 57.93,72.43 U31.122
N1127039: length 2
  BOTTOM w0.102: R439.1 54.37,55.36
  BOTTOM w0.114: 54.37,55.36 54.33,55.41 U31.48
N1127083: length 2.5
  BOTTOM w0.114: U31.77 45.58,62.66 44.67,63.57 R455.2
N1127147: length 5.6
  TOP w0.102: U34.3 49.55,73.85 49.07,74.33 R461.1
N1127169: length 2.1
  TOP w0.102: R460.1 48.28,81.36 U34.7
N1127267: length 2.2
  BOTTOM w0.114: R435.2 54.73,54.8 U31.47
N1127313: length 2.5
  BOTTOM w0.114: R438.2 63.4,65.08 62.58,64.26 U31.16
N1127321: length 8.1
  BOTTOM w0.114: U31.15 62.51,64.66 R422.2 64.45,65.58 65.88,65.58 67.83,63.63 D9.N
N1127467: length 2.4
  BOTTOM w0.114: R395.1 45.02,65.14 45.5,64.66 U31.82
N1127901: length 1.1
  BOTTOM w0.114: U30.12 77.46,69.5 R391.2
N1128819: length 1.1
  BOTTOM w0.114: U32.12 77.46,65.43 R427.2
N1129433: length 3.9
  BOTTOM w0.114: R398.1 46.51,73.74 47.12,73.14 48.09,73.14 48.73,72.5 U31.99
N1129705: length 6.8
  BOTTOM w0.114: R447.2 66.89,60.9 66.55,61.24 66.55,61.91 65.91,62.55 63.15,62.55 62.86,62.26 U31.21
N1129743: length 4.1
  BOTTOM w0.102: R404.1 47.07,72.75 48.04,72.75 48.33,72.46 U31.98
N5550068: length 9.7
  BOTTOM w0.114: U8.H5 178.23,29.12 178.06,28.96 177.36,28.96 176.04,30.28 176.04,30.87 175.87,31.04 175.87,32.83 175.76,32.95 175.46,32.95 175.35,33.06 175.35,33.29 175.46,33.41 175.76,33.41 175.87,33.52 175.87,33.75 175.76,33.86 175.46,33.86 175.35,33.98 175.35,34.21 175.46,34.32 175.76,34.32 175.87,34.44 R157.2
N5550072: length 8.5
  BOTTOM w0.076: 183.97,31.47 183.97,29.37 U8.W5
  BOTTOM w0.114: R576.2 186.54,35.08 R165.2 186.54,34.22 184.69,32.38 184.47,32.38 184.26,32.16 184.26,31.76 183.97,31.47
N5550076: length 9.5
  BOTTOM w0.076: U8.W6 183.48,29.36 183.48,31.5
  BOTTOM w0.114: R167.2 185.65,34.57 185.83,34.39 185.83,34.18 185.52,33.86 185.34,33.86 185.09,34.11 184.95,34.11 184.76,33.92 184.76,33.69 185.04,33.41 185.04,33.25 184.88,33.09 184.65,33.09 184.39,33.36 184.04,33.36 183.87,33.19 183.87,31.9 183.48,31.5
N5550080: length 9.8
  BOTTOM w0.114: R164.2 177.05,34.42 177.05,34.18 177.17,34.06 177.9,34.06 178.03,33.94 178.03,33.7 177.9,33.57 177.17,33.57 177.05,33.46 177.05,33.19 176.94,33.08 176.74,33.08 176.62,32.96 176.62,32.73 176.74,32.62 176.94,32.62 177.05,32.51 177.05,32.28 176.94,32.16 176.74,32.16 176.62,32.05 176.62,31.82 176.74,31.71 176.94,31.71 177.05,31.59 177.05,30.33 177.75,29.62 U8.H4
N5550084: length 5.4
  BOTTOM w0.076: U8.J2 178.96,30.88 178.96,31.52
  BOTTOM w0.102: 178.96,31.54 178.96,31.52
  BOTTOM w0.114: 178.96,31.54 178.96,32.08 181.21,34.33 R162.2
N5550116: length 9
  BOTTOM w0.076: 178.3,29.38 178.96,29.38 U8.J5
  BOTTOM w0.114: 178.3,29.38 178.07,29.38 178,29.31 177.52,29.31 176.4,30.43 176.4,31.12 176.25,31.28 176.25,33.47 176.37,33.58 176.64,33.58 176.76,33.7 176.76,33.93 176.64,34.04 176.37,34.04 176.25,34.15 176.25,34.51 R159.2
N5550120: length 7.1
  BOTTOM w0.114: R158.2 179.43,34.61 179.54,34.49 179.8,34.49 179.93,34.36 179.93,34.15 179.69,33.9 179.49,33.9 178.39,32.81 178,32.81 177.79,32.61 177.79,30.64 178.31,30.12 U8.H3
N5550124: length 7.6
  BOTTOM w0.076: 182.98,31.42 182.98,29.36 U8.U5
  BOTTOM w0.114: 182.98,31.42 183.08,31.52 183.08,32.97 184.76,34.65 R169.2 R168.2
N5550128: length 9.6
  BOTTOM w0.076: 178.41,28.88 178.96,28.88 U8.J6
  BOTTOM w0.114: R156.2 174.98,32.67 175.38,32.27 175.38,30.41 177.21,28.58 178.11,28.58 178.41,28.88
N5550132: length 9.1
  BOTTOM w0.076: 178.16,29.9 178.18,29.88 178.96,29.88 U8.J4
  BOTTOM w0.114: 178.16,29.9 178.05,29.9 177.42,30.54 177.42,33.03 177.57,33.18 178.25,33.18 178.42,33.36 178.42,33.74 178.54,33.86 178.9,33.86 179.14,34.1 179.14,34.32 179.02,34.44 178.32,34.44 178.16,34.6 178.16,34.9 178.27,35.02 R161.2
N5550136: length 6.5
  BOTTOM w0.076: 178.48,30.38 178.96,30.38 U8.J3
  BOTTOM w0.114: R160.2 180.32,34 178.24,31.92 178.24,30.6 178.45,30.38 178.48,30.38
N5560544: length 1.2
  BOTTOM w0.102: U6.12 77.46,60.17 R125.2
N5591752: length 3.9
  TOP w0.178: R196.1 158.12,27.98 159.64,26.46 U11.60
  TOP w0.203: R195.2 R196.1
N5595026: length 4.4
  TOP w0.102: R206.2 R203.2
  TOP w0.114: U11.14 156.8,19.99 155.69,18.87 155.69,18.19 155.29,17.8 R206.2
N5595322: length 23.6
  TOP w0.178: v1(161.48,27.55) 161.64,27.39 U11.55
  BOTTOM w0.508: R194.2 150.06,19.02 150.31,19.27 150.31,22.36 152.85,24.9 152.85,26.58 156.45,30.18 160.98,30.18 161.56,29.6 C183.2 161.56,27.62 v1(161.48,27.55)
N5595880: length 2.3
  TOP w0.178: U11.53 162.44,28.26 C187.1
N5599060: length 10.6
  TOP w0.102: v1(150.08,17.36) 150.55,17.83 Q52.3
  TOP w0.114: U11.15 156.75,19.59 156.46,19.31 156.46,19.09 v1(156.38,19)
  LAY4 w0.102: v1(150.08,17.36) 150.08,18.02 151.51,19.46 155.91,19.46 v1(156.38,19)
  BOTTOM w0.102: v1(156.38,19) 156.31,18.93 R207.1
N5599220: length 4.3
  TOP w0.102: R208.2 R558.1 155.48,16.94
  TOP w0.114: 155.48,16.94 157.1,18.56 157.1,19.15 U11.16
N5599311: length 4.7
  TOP w0.114: U11.27 162.04,17.79 162.59,17.24 162.59,15.17 v1(162.66,15.09)
  BOTTOM w0.102: R589.2 162.4,15.09 v1(162.66,15.09)
N5599330: length 1.9
  TOP w0.114: v1(162,17.23) 161.64,17.59 U11.26
  BOTTOM w0.102: v1(162,17.23) 161.7,16.93 R210.2
N5599357: length 47.8
  TOP w0.114: v1(163.34,15.81) 163.16,15.81 162.89,16.09 162.89,17.28 162.44,17.73 U11.28
  LAY4 w0.102: v1(165.88,15.07) 165.88,15.64 165.29,16.23 165.29,21.57 170.87,27.15 173.88,27.15 174.38,26.65 180.52,26.65 180.97,26.19 187.76,26.19 192.96,31.38 v1(194.69,31.38)
  BOTTOM w0.102: v1(165.88,15.07) 165.88,15.46 165.53,15.81 v1(163.34,15.81) ; v1(194.69,31.38) 194.7,31.39 R588.2
N5601032: length 3.6
  TOP w0.178: U11.35 165.43,19.99 165.59,19.83 166.08,19.83
  TOP w0.381: 166.08,19.83 167.1,18.8 C223.2
N5603445: length 2.4
  TOP w0.178: U11.30 163.24,17.76 164.18,16.81 R211.1
N5604033: length 3.2
  TOP w0.178: U11.5 156.47,23.59 156.27,23.79
  TOP w0.203: 156.27,23.79 154.62,23.79 154.57,23.84
  TOP w0.508: C211.1 154.57,23.84
N5614603: length 1.8
  BOTTOM w0.178: U10.17 123.41,62.16 C165.1
N5614763: length 3.5
  BOTTOM w0.178: R182.2 123.76,59.25 122.65,60.36 U10.1
N5615595: length 3.6
  BOTTOM w0.178: R184.1 118.67,59.22 119.8,59.22 120.4,59.82 U10.5
N5615857: length 2.1
  BOTTOM w0.178: U10.9 119.39,62.16 118.3,63.25 C166.2
N5617013: length 2
  TOP w0.178: v1(157.28,25.65) 157.71,26.08 158.03,26.08 U11.64
  BOTTOM w0.203: v1(157.28,25.65) 157.28,25.26 R198.2
N5627138: length 3.3
  TOP w0.178: U11.41 165.42,22.39
  TOP w0.203: C213.2 167.23,22.19 165.62,22.19 165.42,22.39
N5627940: length 2.4
  TOP w0.178: 165.61,23.99 165.65,24.03 166.39,24.03 v1(166.44,24.08)
  TOP w0.203: U11.45 165.61,23.99
  BOTTOM w0.305: v1(166.44,24.08) 166.45,24.09 R200.1
N6484561: length 2.7
  BOTTOM w0.102: R454.2 44.62,59.93 45.75,61.06 U31.73
N6547424: length 2.5
  TOP w0.203: R259.2 R260.2 149.87,100.39 v1(150.71,100.39)
  BOTTOM w0.152: U16.45 v1(150.71,100.39)
N6549298: length 1.7
  TOP w0.203: U17.7 139.91,96.65 R269.1
N6549760: length 1.9
  BOTTOM w0.102: R268.1 153.05,91.88 153.11,91.94 U16.20
N6556930: length 6.9
  TOP w0.124: CN3.S5 102.36,73.74 102.75,73.35 103.07,73.35 103.33,73.09 103.33,72.44 103.64,72.13 105.87,72.13 106.24,71.75 106.24,71 C433.2
N6556942: length 5.8
  TOP w0.124: CN3.S2 102.98,77.55 103.17,77.35 105.62,77.35 106.24,76.74 106.24,76.34 C429.2
N6556946: length 5.8
  TOP w0.124: CN3.S3 102.98,76.28 103.49,76.78 103.49,76.97 103.61,77.1 105.52,77.1 105.99,76.63 105.99,76.38 C432.2
N6556996: length 6.9
  TOP w0.124: CN3.S6 101.52,72.81 101.81,73.1 102.97,73.1 103.08,72.98 103.08,72.33 103.54,71.87 105.76,71.87 105.99,71.65 105.99,71.17 C434.2
N6563019: length 4.1
  TOP w0.124: J4.3 7.95,92.97 8.86,92.07 8.86,91.84 D14.N 8.53,90.56 FIL5.3
N6563079: length 4.1
  TOP w0.124: FIL7.2 12.32,90.38 U37.2 12.43,91.14 12.43,92.32 12.95,92.84 J4.9
N6563083: length 4.2
  TOP w0.124: FIL7.3 11.62,90.46 U37.1 11.43,91.23 11.43,92.27 10.95,92.74 J4.8
N6563115: length 4.1
  TOP w0.124: J4.2 9.95,92.96 9.11,92.11 9.11,91.84 D13.N 9.44,90.55 FIL5.2
N6563127: length 3.8
  TOP w0.124: FIL6.3 5.55,90.97 U36.1 5.78,91.77 5.78,91.94 4.95,92.76 J4.5
N6564657: length 0.9
  TOP w0.124: C442.1 11.43,87.6 FIL7.4
N6564689: length 3.8
  TOP w0.124: FIL6.2 6.25,90.9 U36.2 6.03,91.76 6.03,91.94 6.95,92.86 J4.6
N6564811: length 5.3
  TOP w0.124: FIL10.3 D20.N 64.88,20.7 67.17,20.7 CN20.3
N6564823: length 5.2
  TOP w0.124: FIL10.2 D19.N 64.88,20.44 67.33,20.44 CN20.2
N6564845: length 0.9
  TOP w0.124: FIL7.1 12.43,87.6 C443.1
N6565949: length 5.1
  TOP w0.124: FIL9.4 47.83,20.03 D17.N 49.25,20.03 49.68,20.45 51.6,20.45 CN19.2
N6565995: length 5.1
  TOP w0.124: CN19.3 51.46,20.71 49.61,20.71 49.29,21.03 D18.N 47.83,21.03 FIL9.1
N6570497: length 3.8
  BOTTOM w0.203: Q51.3 148.77,83.97 149.16,84.36 R540.2 149.89,86.02 Q50.1
N6570755: length 3.8
  BOTTOM w0.203: R537.2 101.3,90.9 Q48.1 101.3,92.8 101,93.09 Q49.3
N6595992: length 2.1
  BOTTOM w0.102: U31.57 50.73,55.31 R552.1
N6596046: length 3.2
  BOTTOM w0.178: U10.7 119.42,61.36 119.19,61.13 118.37,61.13 R187.1
  BOTTOM w0.203: R187.1 118.02,61.38 117.26,62.14 R188.2
N6633155: length 3.7
  BOTTOM w0.305: R347.1 C394.1 J2.4
N6633185: length 3.7
  BOTTOM w0.305: J2.3 28.55,19.01 28.75,19.22 C393.1 R348.1
N6635302: length 7.1
  TOP w0.305: J3.3 28.12,27.93 23.49,27.93 C399.1 22.71,27.53 R352.1
N6635336: length 13.7
  TOP w0.305: R354.1 27.66,31 C398.1 30,30.57 30,29.29 31.23,28.07 34.36,28.07 34.65,28.35 J3.4
N6638078: length 1.2
  BOTTOM w0.305: R334.1 21.84,27.65 C378.1
N6638082: length 1.2
  BOTTOM w0.305: C379.1 23.12,27.66 R336.1
N6697991: length 3.3
  BOTTOM w0.203: 135.94,85.2 135.94,85.89 135.24,86.59 R249.2
N6698007: length 2
  BOTTOM w0.203: C286.2 136.19,88.25 R249.1 136.19,87.1 U15.4
N6698131: length 9.5
  TOP w0.102: v1(134.74,87.43) 135.21,86.95 135.21,85.85 134.95,85.58 133.51,85.58 R251.2 131.23,86.39 Q30.3
  BOTTOM w0.203: v1(134.74,87.43) 134.4,87.76 133.93,87.76 R255.1 133.2,88.08 133.2,87.33 133.44,87.1 U15.3
N6698734: length 5.7
  TOP w0.102: R253.2 132.7,87.34 Q30.1 128.61,87.34 127.66,86.39 Q31.3
N6729809: length 1.4
  BOTTOM w0.203: D5.3 111.93,59.76 C178.2
N6729821: length 3
  BOTTOM w0.203: C181.1 D4.2 D5.1
N6730049: length 3.7
  BOTTOM w0.203: D4.3 110.46,61.11 111.12,60.45 C177.2
N6738242: length 29.1
  BOTTOM w0.305: Q18.4 140.91,62.83 141.89,61.85 148.83,61.85 149.16,61.52 153.26,61.52 154.27,62.53 R217.1 C256.2
N6738428: length 2
  BOTTOM w0.203: Q21.4 C260.2 R222.1
N6738432: length 7.4
  BOTTOM w0.305: Q20.3 155.67,67.95 156.57,68.85 156.57,69.27 157.67,70.37 Q19.1 R216.2 R218.2
N6738496: length 1.4
  BOTTOM w0.203: Q20.1 R219.2
N6739070: length 6
  BOTTOM w0.203: Q23.3 109.63,78.15 111.63,76.15 Q22.1 112.34,75.99 R221.2 113.06,77.55 R224.2
N6739082: length 5.5
  BOTTOM w0.203: R220.2 112.42,74.63 110.89,74.63 110.48,75.04 Q22.3 108.78,75.04 R222.2
N6739106: length 1.1
  BOTTOM w0.203: Q23.1 111.62,79.55 R223.2
N6774197: length 5.5
  BOTTOM w0.508: CN24.1 36.42,74.06 R551.2
N6774217: length 1.3
  BOTTOM w0.508: R551.1 D26.P
N6835771: length 28.8
  TOP w0.381: CN21.D 115.75,18 117.89,15.85 127.89,15.85 128.93,16.9 v1(131.58,16.9)
  BOTTOM w0.508: R494.1 139.43,19.32 138.76,18.65 138.76,18.54 136.71,16.48 131.99,16.48 v1(131.58,16.9)
N6920056: length 2.3
  BOTTOM w0.203: R554.1 C268.2 166.37,36.03 U44.4
N6920082: length 2.6
  BOTTOM w0.305: R559.1 166.35,31.21 R234.2 166.36,31.88 166.37,31.88 U44.3
N6950647: length 1.4
  BOTTOM w0.203: U46.1 142.05,46.01 R557.2
N7015906: length 8.7
  TOP w0.102: U1.AF3 184.15,50.59 183.86,50.31 183.86,50.04 184.09,49.81 184.09,49.34
  TOP w0.114: TP10.1 184.89,43.74 184.89,47.58 184.09,48.38 184.09,49.34
N7019072: length 3.2
  BOTTOM w0.102: Q53.3 159.99,58.83 R592.1 157.71,58.83 R97.1 R95.1
N7027378: length 2.5
  BOTTOM w0.102: 62.86,62.76 62.76,62.66 U31.20
  BOTTOM w0.114: R562.1 63.48,63.38 62.86,62.76
N7088826: length 25.1
  TOP w0.254: v1(182.88,62.23) 182.5,62.61 U1.AC27
  LAY3 w0.203: v1(195.12,48.08) 195.72,48.69 195.72,49.6 194.85,50.47 194.85,56.95 194.54,57.27 191.12,57.27 189.14,59.25 189.14,59.87 188.07,60.94 187.2,60.94 186.48,61.66 183.45,61.66 v1(182.88,62.23)
  BOTTOM w0.203: v1(195.12,48.08) 195.11,48.09 R565.1
N7139654: length 1.5
  BOTTOM w0.102: R113.1 176.1,81.71 Q6.3
N7139690: length 1.3
  BOTTOM w0.102: Q7.3 R123.1
N7139951: length 1.2
  TOP w0.089: U1.U51 179.78,74.14 v1(179.82,74.1)
  BOTTOM w0.102: R567.2 179.84,74.13 v1(179.82,74.1)
N7142786: length 7.9
  TOP w0.102: U1.V4 180.28,51.42 181.22,50.48 181.35,50.48 181.53,50.31 181.53,50.05 181.37,49.89 181.37,49.85
  TOP w0.114: 181.37,49.85 181.37,49.67 181.63,49.42 181.63,48.58 v1(180.99,47.94)
  BOTTOM w0.114: R37.2 179.62,45.95 179.89,46.21 179.89,46.71 180.48,47.31 180.48,47.69 180.74,47.94 v1(180.99,47.94)
N7142796: length 7.3
  TOP w0.102: 180.54,47.77 180.54,49.31 180.47,49.38 180.47,49.95 180.61,50.09 180.61,50.25 180.27,50.59 U1.V3
  TOP w0.114: 180.54,47.77 v1(180.99,47.31)
  BOTTOM w0.114: R38.2 179.36,45.11 180.29,46.04 180.29,46.74 180.87,47.31 v1(180.99,47.31)
N7142806: length 7.2
  TOP w0.102: U1.V2 180.27,47.4
  TOP w0.114: 180.27,47.4 v1(180.99,46.67)
  BOTTOM w0.114: R39.2 179.3,44.26 180.99,45.95 v1(180.99,46.67)
N7142816: length 5.5
  TOP w0.102: 181.25,48.83 181.42,49.01 181.42,49.33 181.16,49.59 181.16,49.83 180.92,50.06 180.92,50.37 U1.W3
  TOP w0.114: 181.25,48.83 v1(180.99,48.58)
  BOTTOM w0.114: R36.2 179.42,46.75 180.1,47.44 180.1,48.07 180.61,48.58 v1(180.99,48.58)
N7143552: length 5.3
  TOP w0.114: U1.V13 180.64,55.31 v1(180.74,55.31)
  BOTTOM w0.114: R569.2 181.25,51.54 181.25,54.8 v1(180.74,55.31)
N7143994: length 2.1
  TOP w0.114: v1(181.75,55.31) 181.62,55.31 U1.Y13
  BOTTOM w0.114: v1(181.75,55.31) 182.64,54.42 TP11.1
N7144188: length 11.6
  TOP w0.114: U1.AF6 184.36,52.2 v1(184.68,52.52)
  BOTTOM w0.114: v1(184.68,52.52) 184.68,52.48 186.85,50.31 186.85,48.53 188.7,46.68 R573.1 188.19,45.87 188.19,44.09 R570.1
N7144196: length 10.7
  TOP w0.114: U1.AH6 184.94,52.14 v1(184.68,51.88)
  BOTTOM w0.114: v1(184.68,51.88) 184.92,51.88 186.6,50.2 186.6,48.25 187.69,47.16 R572.1 187.15,45.84 187.15,44.11 R571.1
N7380328: length 2.1
  TOP w0.203: D28.N 131.49,9.47 Q1.1
N7380332: length 0.9
  TOP w0.203: R3.1 C2.1
N7537612: length 17.4
  TOP w0.102: U1.BA26 191.71,62.12 v1(192.17,61.66)
  LAY3 w0.102: v1(192.17,61.66) 193.23,60.6 194.19,60.6 195.48,59.31 195.48,58.57 198.19,55.86 v1(198.19,48.52)
  BOTTOM w0.102: R593.1 v1(198.19,48.52)
N7539259: length 2.9
  TOP w0.076: v1(172.44,76.01) 172.49,76.06 172.95,76.06 173.2,75.8 173.2,75.74 173.25,75.34 173.1,75.15 172.94,75.13 172.88,75.13 U1.B52
  BOTTOM w0.102: R594.2 172.58,75.87 v1(172.44,76.01)
N7546529: length 9.5
  TOP w0.076: U1.BH52 195.08,74.63 195.2,74.29 195.3,74.11 195.38,74.03
  TOP w0.102: R595.2 198.09,80.21 198.09,75.98 196.84,74.74 195.98,74.74 195.83,74.59 195.83,74.23 195.62,74.03 195.38,74.03
N7553859: length 9.8
  BOTTOM w0.102: U8.H6 178.55,28.62 178.14,28.21 177.07,28.21 175,30.28 175,32.14 174.14,33 R599.1
N7556393: length 120.1
  TOP w0.114: U1.A13 171.77,55.73 170.35,55.73 169.89,56.18 165.17,56.18 163.42,57.93 149.88,57.93 148.79,56.84 138.38,56.84 137.4,55.87 123.2,55.87 120.73,53.4 111.32,53.4 109.66,51.73 106.36,51.73 105.78,52.31 105.78,66.7 103.37,69.11 95.59,69.11 86.52,60.04 v1(84.83,60.04)
  BOTTOM w0.102: R605.1 79.11,56.04 79.81,55.34 82.87,55.34 84.83,57.31 v1(84.83,60.04)
N7556465: length 117.7
  TOP w0.102: U1.C12 172.66,55.32 172.36,55.62 172.11,55.62 171.96,55.47
  TOP w0.114: 171.96,55.47 170.23,55.47 169.74,55.96 165.04,55.96 163.36,57.63 149.88,57.63 148.88,56.63 138.54,56.63 137.52,55.6 123.7,55.6 123.7,55.58 121.17,53.06 111.45,53.06 109.89,51.5 105.95,51.5 105.56,51.88 105.56,66.59 103.36,68.79 96.33,68.79 87.08,59.54 84.24,59.54 v1(83.88,59.9)
  BOTTOM w0.102: R603.1 82.27,57.51 83.88,59.13 v1(83.88,59.9)
N7556469: length 117.4
  TOP w0.114: v1(83.2,60.4) 83.26,60.47 85.86,60.47 86.18,60.78 86.18,61.06 94.56,69.44 103.37,69.44 105.99,66.82 105.99,52.52 106.54,51.97 109.38,51.97 111.09,53.67 120.37,53.67 122.8,56.11 137.24,56.11 138.2,57.06 148.7,57.06 150.03,58.39 163.69,58.39 164.76,57.32 166.54,57.32 167.22,56.64 170.16,56.64 170.64,56.16 171.44,56.16 171.57,56.29 U1.B14
  BOTTOM w0.102: v1(83.2,60.4) 83.2,58.92 82.18,57.9 81.16,57.9 80.77,58.3 R604.1
N7556492: length 9.8
  TOP w0.102: U1.F14 174.2,56.14 v1(173.88,55.82)
  LAY3 w0.127: v1(168.1,51.42) 169.25,51.42 172.12,54.29 172.12,55.38 172.96,56.22 173.61,56.22 173.88,55.95 v1(173.88,55.82)
  BOTTOM w0.114: R602.1 v1(168.1,51.42)
N7642832: length 1
  TOP w0.508: R840.1 C691.1
N7643520: length 1.4
  TOP w0.406: C822.1 158.8,11.37 158.64,11.37 R841.1
N7679816: length 8.5
  BOTTOM w0.076: U8.R5 182.33,29.24 182.33,29.62 181.97,29.98 181.97,31.55
  BOTTOM w0.102: 181.97,32.09 181.97,31.55
  BOTTOM w0.114: R598.2 182.6,34 181.97,33.37 181.97,32.09
N7679820: length 6.4
  BOTTOM w0.076: 182.47,31.55 182.47,29.88 182.72,29.63 U8.T5
  BOTTOM w0.102: 182.29,33.2 182.29,31.73 182.47,31.55
  BOTTOM w0.114: 182.29,33.2 183.09,34 R597.2
N16712559: length 2.8
  BOTTOM w0.381: R375.1 C412.2 215.85,12.79 216.42,13.36 U28.4
N16712977: length 2.1
  TOP w0.102: CN26.58 v1(229.38,14.52)
  BOTTOM w0.102: R784.1 229.26,14.4 v1(229.38,14.52)
N16713003: length 2.2
  TOP w0.102: CN26.60 229.73,14.02 v1(229.37,13.65)
  BOTTOM w0.102: R785.1 229.3,13.59 v1(229.37,13.65)
N16713393: length 1.8
  TOP w0.102: CN26.50 v1(231.71,16.52)
  BOTTOM w0.102: R788.1 232.38,16.52 v1(231.71,16.52)
N16713507: length 2.9
  TOP w0.102: v1(236.1,14.8) 236.57,15.27 CN26.55
  BOTTOM w0.102: R787.2 236.07,14.77 v1(236.1,14.8)
N16714785: length 3.7
  BOTTOM w0.102: R365.2 222.73,24.57 Q40.3 222.74,23.28 Q39.1
N16872587: length 3.5
  BOTTOM w0.102: U31.100 49.13,72.59 48.29,73.43 47.67,73.43 47.32,73.77 R828.1
N16888466: length 4
  TOP w0.124: R2981.2 35.99,91.18 35.99,91.44 D2513.N 36.85,92.3 CN18.2
N16888468: length 3.9
  TOP w0.124: FIL16.3 32.47,90.61 U2523.1 32.47,91.67 31.85,92.29 CN18.5
N16888488: length 1
  TOP w0.124: C2762.1 42.65,89.32 FIL14.4
N16888504: length 4
  TOP w0.124: FIL16.2 33.17,90.71 U2523.2 33.17,91.61 33.85,92.3 CN18.6
N16888506: length 5.8
  TOP w0.124: R2979.2 39.54,89.91 39.31,89.91 39.13,90.09 U2524.2 39.01,90.18 38.92,90.28 38.92,90.88 39.85,91.82 CN18.9
N16888527: length 1
  TOP w0.124: C2763.1 42.3,90.32 41.69,90.32 FIL14.1
N16888529: length 4
  TOP w0.124: R2980.2 35.74,91.18 35.74,91.44 D2512.N 34.85,92.32 CN18.3
N16888618: length 6.2
  TOP w0.124: CN18.8 37.85,91.65 38.67,90.84 38.67,89.95 U2524.1 39.78,89.48 R2978.2
